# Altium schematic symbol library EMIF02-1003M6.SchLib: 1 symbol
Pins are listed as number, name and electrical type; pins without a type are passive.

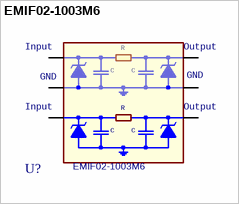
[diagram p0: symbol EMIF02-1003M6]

## EMIF02-1003M6
designator U?
footprint ST_QFN50P145X100X55-6L
pins: 1 Input1, 2 GND, 3 Input2, 4 Output2, 5 GND1, 6 Output1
